// Mitsubishi GX Works2 project: 8键点动8灯，松开时根据按下时的先后顺序点亮剩下灯(1)   PLC: FX3U/FX3UC

PROGRAM MAIN
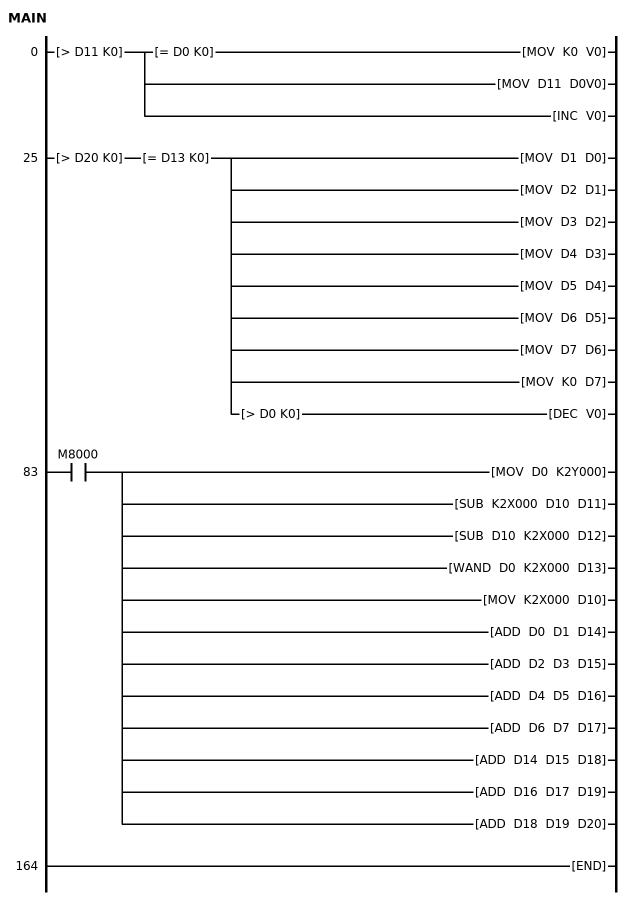
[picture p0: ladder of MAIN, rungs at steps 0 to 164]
0     LD>     D11 K0
      MPS
      AND=    D0 K0
      MOV     K0 V0
        [note] 将K0存入V0
      MPP
      MOV     D11 D0V0
      INC     V0
        [note] V0自加一
25    LD>     D20 K0
      AND=    D13 K0
      MOV     D1 D0
      MOV     D2 D1
      MOV     D3 D2
      MOV     D4 D3
      MOV     D5 D4
      MOV     D6 D5
      MOV     D7 D6
      MOV     K0 D7
      AND>    D0 K0
      DEC     V0
        [note] V0自减一
83    LD      M8000
      MOV     D0 K2Y000
      SUB     K2X000 D10 D11
      SUB     D10 K2X000 D12
      WAND    D0 K2X000 D13
      MOV     K2X000 D10
      ADD     D0 D1 D14
      ADD     D2 D3 D15
      ADD     D4 D5 D16
      ADD     D6 D7 D17
      ADD     D14 D15 D18
      ADD     D16 D17 D19
      ADD     D18 D19 D20
164   END
END_PROGRAM
